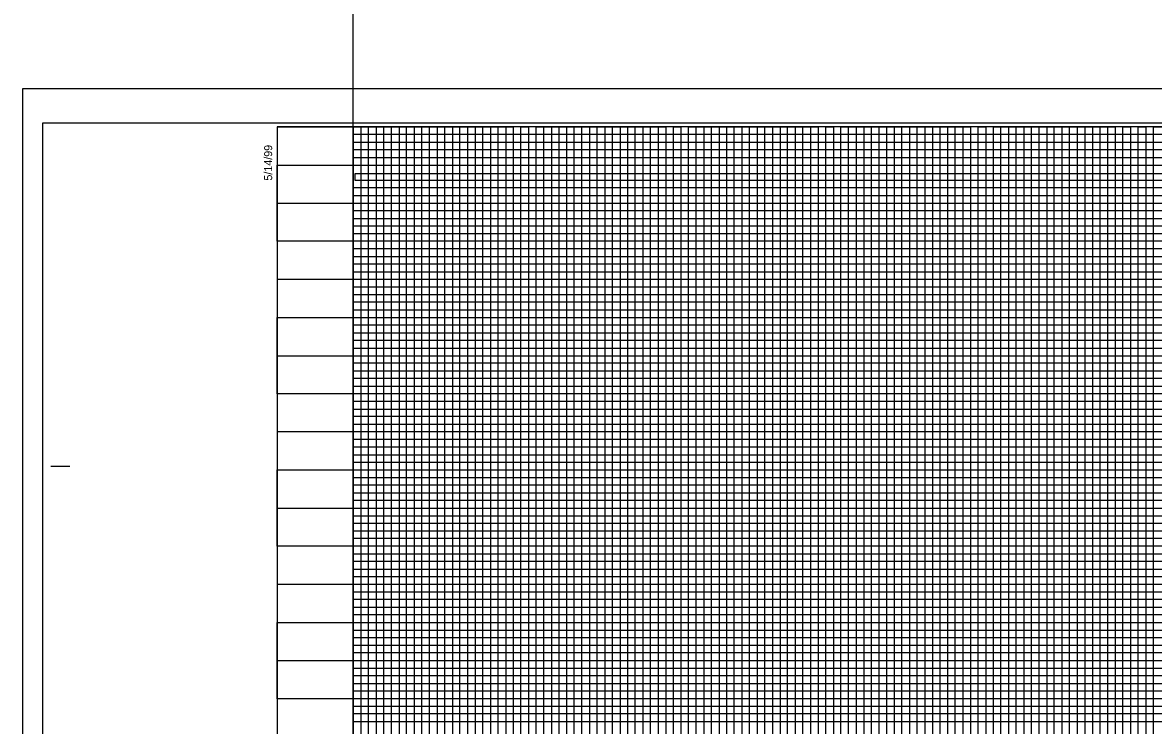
# Model space of a CAD drawing. Extents: x 2345490 to 2436403, y 465165 to 573888.
# Drawn here: x 2410678 to 2411420, y 533128 to 533589 of the extents above; entities that cross this region are included whole.
import ezdxf

# ---------------------------------------------------------------- set-up
doc = ezdxf.new("R2010")
doc.units = 0
for name, color, linetype in [('Old_Level_18', 7, 'Continuous'), ('Old_Level_41', 7, 'Continuous'), ('Old_Level_42', 7, 'Continuous'), ('Old_Level_43', 7, 'Continuous'), ('Old_Level_50', 7, 'Continuous'), ('Old_Level_51', 7, 'Continuous'), ('Old_Level_63', 7, 'Continuous')]:
    doc.layers.add(name, color=color, linetype=linetype)

msp = doc.modelspace()

# ---------------------------------------------------------------- linework, layer by layer
at = {"layer": 'Old_Level_18'}
msp.add_lwpolyline([(2412345.325, 533520.5875), (2410845.325, 533520.5875), (2410845.325, 532470.5875), (2412345.325, 532470.5875)], close=True, dxfattribs=at)
at = {"layer": 'Old_Level_41'}
msp.add_line((2410696.825, 533298.0875), (2410709.325, 533298.0875), dxfattribs=at)
for points in [[(2410845.325, 533520.5875), (2410895.325, 533520.5875), (2410895.325, 532495.5875), (2410945.325, 532495.5875), (2410945.325, 533520.5875), (2410995.325, 533520.5875), (2410995.325, 532495.5875), (2411045.325, 532495.5875), (2411045.325, 533520.5875), (2411095.325, 533520.5875), (2411095.325, 532495.5875), (2411145.325, 532495.5875), (2411145.325, 533520.5875), (2411195.325, 533520.5875), (2411195.325, 532495.5875), (2411245.325, 532495.5875), (2411245.325, 533520.5875), (2411295.325, 533520.5875), (2411295.325, 532495.5875), (2411345.325, 532495.5875), (2411345.325, 533520.5875), (2411395.325, 533520.5875), (2411395.325, 532495.5875), (2411445.325, 532495.5875)], [(2410920.325, 532495.5875), (2410920.325, 533520.5875), (2410970.325, 533520.5875), (2410970.325, 532495.5875), (2411020.325, 532495.5875), (2411020.325, 533520.5875), (2411070.325, 533520.5875), (2411070.325, 532495.5875), (2411120.325, 532495.5875), (2411120.325, 533520.5875), (2411170.325, 533520.5875), (2411170.325, 532495.5875), (2411220.325, 532495.5875), (2411220.325, 533520.5875), (2411270.325, 533520.5875), (2411270.325, 532495.5875), (2411320.325, 532495.5875), (2411320.325, 533520.5875), (2411370.325, 533520.5875), (2411370.325, 532495.5875), (2411420.325, 532495.5875), (2411420.325, 533520.5875), (2411470.325, 533520.5875)], [(2410845.325, 533470.5875), (2412145.275, 533470.5875)], [(2412145.275, 533420.5875), (2410845.325, 533420.5875), (2410845.325, 533370.5375), (2412345.325, 533370.5375)], [(2412345.325, 533345.5875), (2410845.325, 533345.5875), (2410845.325, 533395.5875), (2412145.275, 533395.5875)], [(2412345.325, 533320.5875), (2410845.325, 533320.5875), (2410845.325, 533270.5875), (2412345.325, 533270.5875)], [(2412345.325, 533245.5875), (2410845.325, 533245.5875), (2410845.325, 533295.5875), (2412345.325, 533295.5875)], [(2412345.325, 533220.5875), (2410845.325, 533220.5875), (2410845.325, 533170.5875), (2412345.325, 533170.5875)]]:
    msp.add_lwpolyline(points, dxfattribs=at)
at = {"layer": 'Old_Level_42'}
for points in [[(2412145.275, 533445.5875), (2410845.425, 533445.5875), (2410845.425, 533495.5375), (2412145.275, 533495.5375)], [(2412345.325, 533145.5875), (2410845.325, 533145.5875), (2410845.325, 533195.5875), (2412345.325, 533195.5875)]]:
    msp.add_lwpolyline(points, dxfattribs=at)
at = {"layer": 'Old_Level_43'}
for p, q in [((2412295.325, 533340.5875), (2410895.325, 533340.5875)), ((2410895.325, 533340.5875), (2410895.325, 533335.5875)), ((2410895.325, 533335.5875), (2412295.325, 533335.5875)), ((2412295.325, 533315.5875), (2410895.325, 533315.5875))]:
    msp.add_line(p, q, dxfattribs=at)
for points in [[(2410900.325, 533520.5875), (2410905.325, 533520.5875), (2410910.325, 533520.5875), (2410915.325, 533520.5875), (2410925.325, 533520.5875), (2410892.275, 533520.5875), (2410897.275, 533520.5875), (2410855.325, 533520.5875), (2410860.325, 533520.5875), (2410865.325, 533520.5875), (2410875.325, 533520.5875), (2410880.325, 533520.5875), (2410885.325, 533520.5875), (2410890.325, 533520.5875), (2410900.325, 533520.5875), (2410900.325, 532495.5875)], [(2410905.325, 532495.5875), (2410905.325, 533520.5875), (2410910.325, 533520.5875), (2410910.325, 532495.5875)], [(2410915.325, 532495.5875), (2410915.325, 533520.5875), (2410925.325, 533520.5875), (2410925.325, 532495.5875)], [(2410930.325, 532495.5875), (2410930.325, 533520.5875), (2410935.325, 533520.5875), (2410935.325, 532495.5875)], [(2410940.325, 532495.5875), (2410940.325, 533520.5875), (2410950.325, 533520.5875), (2410950.325, 532495.5875)], [(2410955.325, 532495.5875), (2410955.325, 533520.5875), (2410960.325, 533520.5875), (2410960.325, 532495.5875)], [(2410965.325, 532495.5875), (2410965.325, 533520.5875), (2410975.325, 533520.5875), (2410975.325, 532495.5875)], [(2410980.325, 532495.5875), (2410980.325, 533520.5875), (2410985.325, 533520.5875), (2410985.325, 532495.5875)], [(2410990.325, 532495.5875), (2410990.325, 533520.5875), (2411000.325, 533520.5875), (2411000.325, 532495.5875)], [(2411005.325, 532495.5875), (2411005.325, 533520.5875), (2411010.325, 533520.5875), (2411010.325, 532495.5875)], [(2411015.325, 532495.5875), (2411015.325, 533520.5875), (2411025.325, 533520.5875), (2411025.325, 532495.5875)], [(2411030.325, 532495.5875), (2411030.325, 533520.5875), (2411035.325, 533520.5875), (2411035.325, 532495.5875)], [(2411040.325, 532495.5875), (2411040.325, 533520.5875), (2411050.325, 533520.5875), (2411050.325, 532495.5875)], [(2411055.325, 532495.5875), (2411055.325, 533520.5875), (2411060.325, 533520.5875), (2411060.325, 532495.5875)], [(2411065.325, 532495.5875), (2411065.325, 533520.5875), (2411075.325, 533520.5875), (2411075.325, 532495.5875)], [(2411080.325, 532495.5875), (2411080.325, 533520.5875), (2411085.325, 533520.5875), (2411085.325, 532495.5875)], [(2411090.325, 532495.5875), (2411090.325, 533520.5875), (2411100.325, 533520.5875), (2411100.325, 532495.5875)], [(2411105.325, 532495.5875), (2411105.325, 533520.5875), (2411105.325, 533520.5875), (2411110.325, 533520.5875), (2411110.325, 532495.5875)], [(2411115.325, 532495.5875), (2411115.325, 533520.5875), (2411125.325, 533520.5875), (2411125.325, 532495.5875)], [(2411130.325, 532495.5875), (2411130.325, 533520.5875), (2411135.325, 533520.5875), (2411135.325, 532495.5875)], [(2411140.325, 532495.5875), (2411140.325, 533520.5875), (2411150.325, 533520.5875), (2411150.325, 532495.5875)], [(2411155.325, 532495.5875), (2411155.325, 533520.5875), (2411160.325, 533520.5875), (2411160.325, 532495.5875)], [(2411165.325, 532495.5875), (2411165.325, 533520.5875), (2411175.325, 533520.5875), (2411175.325, 532495.5875)], [(2411180.325, 532495.5875), (2411180.325, 533520.5875), (2411185.325, 533520.5875), (2411185.325, 532495.5875)], [(2411190.325, 532495.5875), (2411190.325, 533520.5875), (2411200.325, 533520.5875), (2411200.325, 532495.5875)], [(2411205.325, 532495.5875), (2411205.325, 533520.5875), (2411210.325, 533520.5875), (2411210.325, 532495.5875)], [(2411215.325, 532495.5875), (2411215.325, 533520.5875), (2411225.325, 533520.5875), (2411225.325, 532495.5875)], [(2411230.325, 533520.5875), (2411230.325, 532495.5875), (2411235.325, 532495.5875), (2411235.325, 533520.5875)], [(2411240.325, 532495.5875), (2411240.325, 533520.5875), (2411250.325, 533520.5875), (2411250.325, 532495.5875)], [(2411255.325, 532495.5875), (2411255.325, 533520.5875), (2411260.325, 533520.5875), (2411260.325, 532495.5875)], [(2411265.325, 532495.5875), (2411265.325, 533520.5875), (2411275.325, 533520.5875), (2411275.325, 532495.5875)], [(2411280.325, 532495.5875), (2411280.325, 533520.5875), (2411285.325, 533520.5875), (2411285.325, 532495.5875)], [(2411290.325, 532495.5875), (2411290.325, 533520.5875), (2411300.325, 533520.5875), (2411300.325, 532495.5875)], [(2411305.325, 532495.5875), (2411305.325, 533520.5875), (2411310.325, 533520.5875), (2411310.325, 532495.5875)], [(2411315.325, 532495.5875), (2411315.325, 533520.5875), (2411325.325, 533520.5875), (2411325.325, 532495.5875)], [(2411330.325, 532495.5875), (2411330.325, 533520.5875), (2411335.325, 533520.5875), (2411335.325, 532495.5875)], [(2411340.325, 532495.5875), (2411340.325, 533520.5875), (2411350.325, 533520.5875), (2411350.325, 532495.5875)], [(2411355.325, 532495.5875), (2411355.325, 533520.5875), (2411360.325, 533520.5875), (2411360.325, 532495.5875)], [(2411365.325, 532495.5875), (2411365.325, 533520.5875), (2411375.325, 533520.5875), (2411375.325, 532495.5875)], [(2411380.325, 533520.5875), (2411380.325, 532495.5875), (2411385.325, 532495.5875), (2411385.325, 533520.5875), (2411390.325, 533520.5875), (2411390.325, 532495.5875), (2411400.325, 532495.5875), (2411400.325, 533520.5875), (2411405.325, 533520.5875), (2411405.325, 532495.5875), (2411410.325, 532495.5875), (2411410.325, 533520.5875), (2411415.325, 533520.5875), (2411415.325, 532495.5875)], [(2412145.275, 533515.5875), (2410895.325, 533515.5875), (2410895.325, 533510.5875), (2412145.275, 533510.5875)], [(2411230.325, 533519.9875), (2411230.325, 532495.5875), (2411235.325, 532495.5875), (2411235.325, 533519.9875)], [(2412145.275, 533505.5875), (2410895.325, 533505.5875), (2410895.325, 533500.5875), (2412145.275, 533500.5875)], [(2412145.275, 533489.8375), (2410896.325, 533489.8375), (2410896.325, 533485.5875), (2412145.275, 533485.5875)], [(2412145.275, 533480.5875), (2410895.325, 533480.5875), (2410895.325, 533475.5875), (2412145.275, 533475.5875)], [(2412145.275, 533465.5875), (2410895.325, 533465.5875), (2410895.325, 533460.5875), (2412145.275, 533460.5875)], [(2412145.275, 533455.5875), (2410895.325, 533455.5875), (2410895.325, 533450.5875), (2412145.275, 533450.5875)], [(2412145.275, 533440.5875), (2410895.325, 533440.5875), (2410895.325, 533435.5875), (2412145.275, 533435.5875)], [(2412145.275, 533430.5875), (2410895.325, 533430.5875), (2410895.325, 533425.5875), (2412145.275, 533425.5875)], [(2412145.275, 533415.5875), (2410895.325, 533415.5875), (2410895.325, 533410.5875), (2412145.275, 533410.5875)], [(2412145.275, 533405.5875), (2410895.325, 533405.5875), (2410895.325, 533400.5875), (2412145.275, 533400.5875)], [(2412145.275, 533390.5875), (2410895.325, 533390.5875), (2410895.325, 533385.5875), (2412145.275, 533385.5875)], [(2412295.325, 533380.5875), (2410895.325, 533380.5875), (2410895.325, 533380.5875), (2410895.325, 533360.5875), (2412295.325, 533360.5875)], [(2410895.325, 533375.5875), (2412295.325, 533375.5875)], [(2412295.325, 533365.5875), (2410895.325, 533365.5875)], [(2412295.325, 533355.5875), (2410895.325, 533355.5875), (2410895.325, 533350.5875), (2412295.325, 533350.5875)], [(2412295.325, 533330.5875), (2410895.325, 533330.5875), (2410895.325, 533325.5875), (2412295.325, 533325.5875)], [(2412295.325, 533310.5875), (2410895.325, 533310.5875), (2410895.325, 533305.5875), (2412295.325, 533305.5875)], [(2412295.325, 533300.5875), (2410895.325, 533300.5875)], [(2410895.325, 533290.5875), (2412295.325, 533290.5875)], [(2412295.325, 533285.5875), (2410895.325, 533285.5875), (2410895.325, 533280.5875), (2412295.325, 533280.5875)], [(2412295.325, 533275.5875), (2410895.325, 533275.5875), (2410895.325, 533265.5875), (2412295.325, 533265.5875)], [(2412295.325, 533260.5875), (2410895.325, 533260.5875), (2410895.325, 533255.5875), (2412295.325, 533255.5875)], [(2412295.325, 533250.5875), (2410895.325, 533250.5875), (2410895.325, 533240.5875), (2412295.325, 533240.5875)], [(2412295.325, 533235.5875), (2410895.325, 533235.5875), (2410895.325, 533230.5875), (2412295.325, 533230.5875)], [(2412295.325, 533225.5875), (2410895.325, 533225.5875), (2410895.325, 533215.5875), (2412295.325, 533215.5875)], [(2412295.325, 533210.5875), (2410895.325, 533210.5875), (2410895.325, 533205.5875), (2412295.325, 533205.5875)], [(2412295.325, 533200.5875), (2410895.325, 533200.5875), (2410895.325, 533190.5875), (2412295.325, 533190.5875)], [(2412295.325, 533185.5875), (2410895.325, 533185.5875), (2410895.325, 533180.5875), (2412295.325, 533180.5875)], [(2412295.325, 533175.5875), (2410895.325, 533175.5875), (2410895.325, 533165.5875), (2412295.325, 533165.5875)], [(2412295.325, 533160.5875), (2410895.325, 533160.5875), (2410895.325, 533155.5875), (2412295.325, 533155.5875)], [(2412295.325, 533150.5875), (2410895.325, 533150.5875), (2410895.325, 533140.5875), (2412295.325, 533140.5875)], [(2412295.325, 533135.5875), (2410895.325, 533135.5875), (2410895.325, 533130.5875), (2412295.325, 533130.5875)]]:
    msp.add_lwpolyline(points, dxfattribs=at)
at = {"layer": 'Old_Level_50'}
msp.add_lwpolyline([(2412357.825, 533523.1375), (2410691.325, 533523.1375), (2410691.325, 532468.0375), (2412357.825, 532468.0375)], close=True, dxfattribs=at)
at = {"layer": 'Old_Level_51'}
msp.add_lwpolyline([(2412362.325, 533545.5875), (2410678.325, 533545.5875), (2410678.325, 532445.5875), (2412362.325, 532445.5875)], close=True, dxfattribs=at)
at = {"layer": 'Old_Level_63'}
msp.add_line((2410895.325, 532495.5875), (2410895.325, 534995.5875), dxfattribs=at)

# ---------------------------------------------------------------- texts
at = {"layer": 'Old_Level_41'}
msp.add_text('5/14/99', height=5.25, rotation=90, dxfattribs=at).set_placement((2410842.075, 533485.3875))

doc.saveas('drawing.dxf')
